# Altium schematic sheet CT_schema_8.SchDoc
size 368 x 243 mm
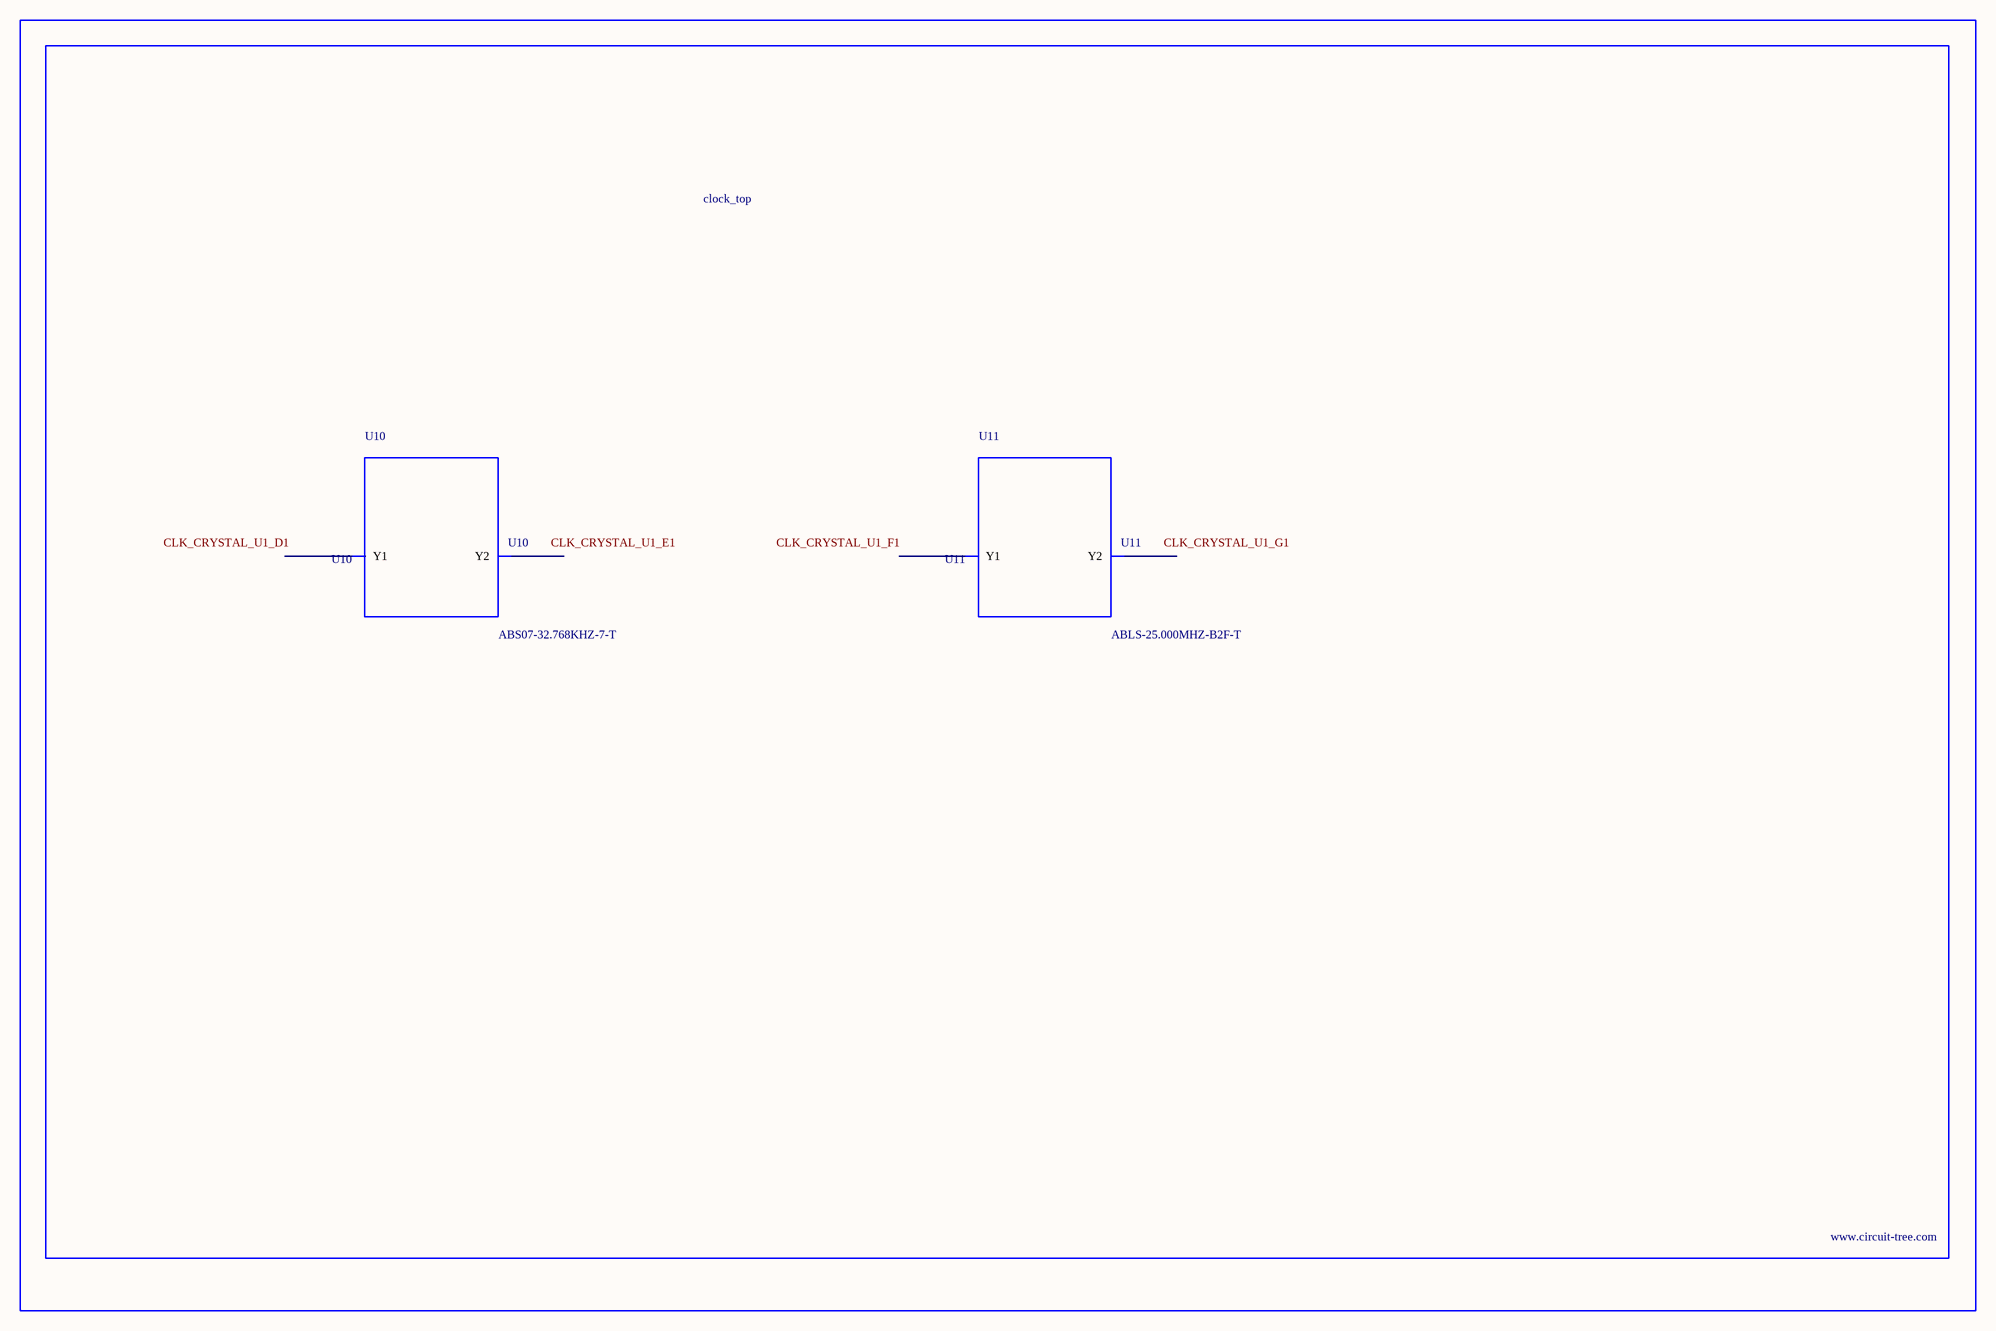
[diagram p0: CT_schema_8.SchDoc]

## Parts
BORDER7  (no value)
U10  ABS07-32.768KHZ-7-T  [ABS07-32.768KHZ-7-T]
U11  ABLS-25.000MHZ-B2F-T  [ABLS-25.000MHZ-B2F-T]

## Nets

Not connected (* = marked no-connect by the designer): U10 1(Y1) 2(Y2); U11 1(Y1) 2(Y2)

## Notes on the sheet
- Labels drawn without touching a wire or pin: CLK_CRYSTAL_U1_D1, CLK_CRYSTAL_U1_E1, CLK_CRYSTAL_U1_F1, CLK_CRYSTAL_U1_G1

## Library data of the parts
BORDER7 = BORDER_PAGE7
